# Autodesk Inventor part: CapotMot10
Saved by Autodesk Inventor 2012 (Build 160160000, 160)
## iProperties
Created: 2013-08
Part Number: CapotMot10
Material: Default
Document SubType Name: Modeling
Designer: hilarion
Density: 1 g/cm^3
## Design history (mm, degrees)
node "CapotMot101"
node "CapotMot10"
node "Base1"
